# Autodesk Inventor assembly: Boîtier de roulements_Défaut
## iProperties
Shininess: 64.0
Length Units: 11269
Angle Units: 11279
Time Units: 11290
Mass Units: 11283
Length Display Precision: 3
Angle Display Precision: 2
Compacted: True
Created: 2006-01
Part Number: Boîtier de roulements_Défaut
Document SubType Name: Assembly
Designer: riri
Density: 0.0
Volumn: 0.0
Area: 0.0
PropertySet Name: Model Information
Control State: 0
Master: False
Checked Out: False
Author: riri
